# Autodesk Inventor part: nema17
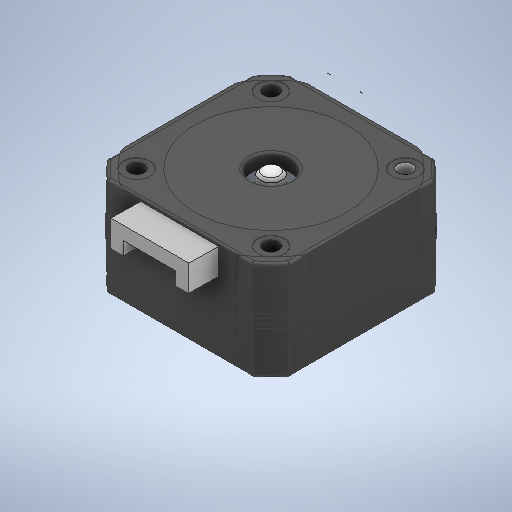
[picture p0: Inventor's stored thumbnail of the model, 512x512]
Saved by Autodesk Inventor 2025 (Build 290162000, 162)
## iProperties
Created: 2022-12
Part Number: nema17
Material: Titanio
Document SubType Name: Modeling
Designer: Ryzen5700u
Density: 4.51 g/cm^3
Appearance: Default
Author: Ryzen5700u
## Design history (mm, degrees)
feature "Solido1"
feature "Solido1:1"
feature "Solido1:2"
feature "Solido2:1"
feature "Solido3:1"
node "Solido2"
node "Solido3"
node "Solido4"
node "Solido5"
node "Solido6"
